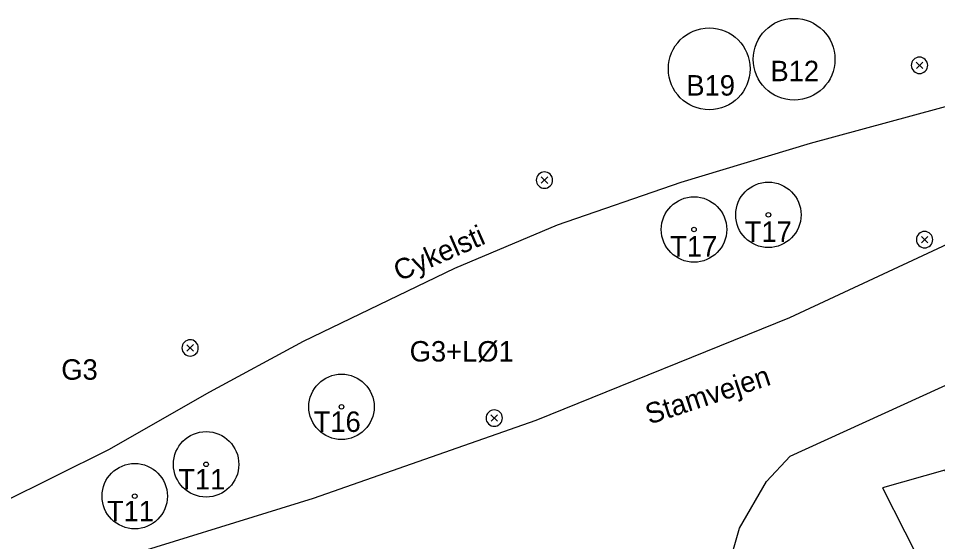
# Model space of a CAD drawing. Extents: x 0 to 512122, y 0 to 6212554.
# Drawn here: x 511644.8 to 511701, y 6211790.6 to 6211822.6 of the extents above; entities that cross this region are included whole.
import ezdxf

# ---------------------------------------------------------------- set-up
doc = ezdxf.new("R2010")
doc.units = 0
for name, color, linetype in [('_lights', 7, 'Continuous'), ('_LØ1', 7, 'Continuous'), ('L40 jord udlagt muld og grøft', 7, 'Continuous'), ('Skel', 7, 'Continuous'), ('TV_U_AFM_Symbl_Gul', 7, 'Continuous'), ('TV_U_LYS_Mastenummer', 7, 'Continuous')]:
    doc.layers.add(name, color=color, linetype=linetype)

# ---------------------------------------------------------------- blocks, each defined once
blk = doc.blocks.new('SOLITAIRE TREES')
at = {"layer": 'Skel'}
for radius in [2, 0.141]:
    blk.add_circle((0, 0), radius, dxfattribs=at)

msp = doc.modelspace()

# ---------------------------------------------------------------- linework, layer by layer
at = {"layer": '_lights'}
for p, q in [((511699.739, 6211819.931), (511700.133, 6211819.537)), ((511700.137, 6211819.935), (511699.743, 6211819.541)), ((511676.802, 6211812.911), (511677.196, 6211812.517)), ((511677.2, 6211812.915), (511676.806, 6211812.521)), ((511700.049, 6211809.272), (511700.443, 6211808.878)), ((511700.447, 6211809.276), (511700.053, 6211808.882)), ((511655.132, 6211802.654), (511655.526, 6211802.26)), ((511655.53, 6211802.658), (511655.136, 6211802.264)), ((511673.729, 6211798.362), (511674.123, 6211797.968)), ((511674.127, 6211798.366), (511673.733, 6211797.972))]:
    msp.add_line(p, q, dxfattribs=at)
for centre, start, end in [((511699.936, 6211819.734), 315.5636, 315), ((511699.936, 6211819.734), 315, 315.5636), ((511676.999, 6211812.714), 315.5636, 315), ((511676.999, 6211812.714), 315, 315.5636), ((511700.246, 6211809.075), 315.5636, 315), ((511700.246, 6211809.075), 315, 315.5636), ((511655.329, 6211802.457), 315.5636, 315), ((511655.329, 6211802.457), 315, 315.5636), ((511673.926, 6211798.165), 315.5636, 315), ((511673.926, 6211798.165), 315, 315.5636)]:
    msp.add_arc(centre, 0.5, start, end, dxfattribs=at)
at = {"layer": '_LØ1'}
msp.add_lwpolyline([(511702.714, 6211817.514), (511693.252, 6211814.953), (511685.346, 6211812.561), (511677.773, 6211809.954), (511671.505, 6211807.315), (511662.231, 6211802.844), (511656.509, 6211799.747), (511650.335, 6211796.231), (511643.776, 6211792.971), (511634.493, 6211789.017), (511624.846, 6211785.675), (511625.405, 6211783.248), (511637.482, 6211785.992), (511649.559, 6211789.163), (511662.877, 6211793.269), (511676.5, 6211798.047), (511692.013, 6211804.326), (511708.572, 6211812.03)], dxfattribs=at)
at = {"layer": 'L40 jord udlagt muld og grøft'}
msp.add_lwpolyline([(511697.82, 6211781.325), (511690.461, 6211779.381), (511688.599, 6211783.339), (511688.247, 6211785.796), (511688.218, 6211788.948), (511688.919, 6211791.428), (511690.581, 6211794.293), (511692.017, 6211795.84), (511714.827, 6211806.237), (511721.141, 6211789.582), (511707.423, 6211784.585), (511701.486, 6211794.988), (511697.668, 6211793.905), (511703.13, 6211783.132)], close=True, dxfattribs=at)
at = {"layer": 'TV_U_LYS_Mastenummer'}
for centre in [(511692.268, 6211820.104), (511692.268, 6211820.104), (511687.076, 6211819.52), (511687.076, 6211819.52)]:
    msp.add_circle(centre, 2.5, dxfattribs=at)

# ---------------------------------------------------------------- block references
at = {"layer": 'Skel'}
for p in [(511690.694, 6211810.594), (511686.146, 6211809.697), (511664.586, 6211798.854), (511656.305, 6211795.337), (511651.94, 6211793.391)]:
    msp.add_blockref('SOLITAIRE TREES', p, dxfattribs=at)

# ---------------------------------------------------------------- texts
at = {"layer": 'TV_U_AFM_Symbl_Gul'}
for s, p in [('B12', (511690.821, 6211818.763)), ('B19', (511685.677, 6211817.883)), ('T17', (511689.248, 6211808.936)), ('T17', (511684.688, 6211808.039)), ('G3+LØ1', (511668.755, 6211801.624)), ('G3', (511647.448, 6211800.511)), ('T16', (511662.883, 6211797.319)), ('T11', (511654.602, 6211793.802)), ('T11', (511650.237, 6211791.856))]:
    msp.add_text(s, height=1.25, dxfattribs=at).set_placement(p)
for s, rotation, p in [('Cykelsti', 23.6442, (511668.115, 6211806.511)), ('Stamvejen', 18.1138, (511683.419, 6211797.766))]:
    msp.add_text(s, height=1.25, rotation=rotation, dxfattribs=at).set_placement(p)

doc.saveas('drawing.dxf')
